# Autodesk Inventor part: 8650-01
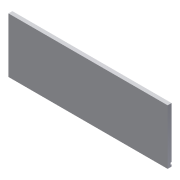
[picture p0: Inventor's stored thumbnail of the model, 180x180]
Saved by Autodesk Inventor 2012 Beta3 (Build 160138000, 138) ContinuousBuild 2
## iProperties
Created: 2011-02
Part Number: 8650-01
Material: Default
Document SubType Name: Modeling
Designer: Beta-8540w
Density: 1 g/cm^3
Author: Beta-8540w
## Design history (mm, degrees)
sketch "Sketch1"
  geometry: L1 (-257.175, -88.9)-(257.175, -88.9); L2 (257.175, -88.9)-(257.175, 88.9); L3 (257.175, 88.9)-(-257.175, 88.9); L4 (-257.175, 88.9)-(-257.175, -88.9); 3 further points
  constraints: 8 end point, 2 midpoint, 2 parallel, 1 horizontal, 1 horizontal alignment, 1 perpendicular, 1 vertical alignment
  dimensions: "drawer_depth" = 514.35 distance of L3.end L2.end; "drawer_side_height" = 177.8 distance of L2.end L1.end
extrude "Extrusion1" new body sketch "Sketch1" distance "d2" = 12.7; taper "d3" = 0 deg
sketch "Sketch2"
  geometry: L1 (257.175, -88.9)-(-257.175, -88.9) reference; L2 (257.175, 88.9)-(257.175, -88.9) reference; L3 (-257.175, -88.9)-(-257.175, 88.9) reference; L4 (-257.175, -82.55)-(257.175, -82.55); L5 (257.175, -82.55)-(257.175, -76.2); L6 (257.175, -76.2)-(-257.175, -76.2); L7 (-257.175, -76.2)-(-257.175, -82.55); 1 further point
  constraints: 8 end point, 2 parallel, 2 point on line, 1 horizontal, 1 perpendicular
  dimensions: "d4" = 6.35 distance between parallel lines of L1 L4; "bottom_thickness" = 6.35 distance of L6.end L4.start
extrude "Extrusion2" cut sketch "Sketch2" distance "d6" = 3.302; taper "d7" = 0 deg
body "Solid1"
